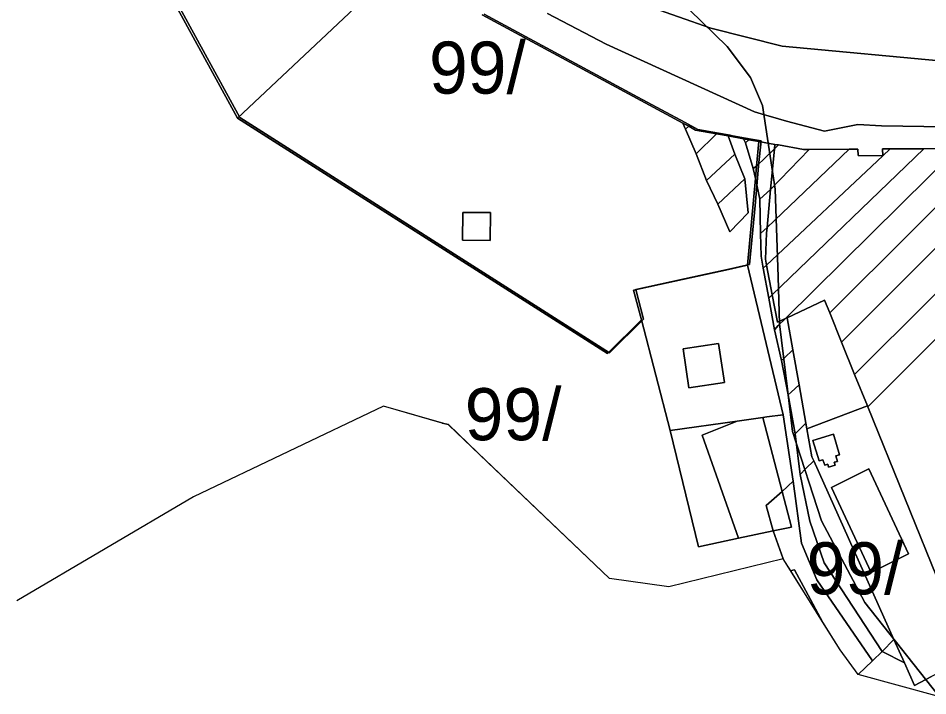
# Model space of a CAD drawing. Extents: x -535894 to -532827, y -1165802 to -1163635.
# Drawn here: x -533561 to -533298.8, y -1165099.9 to -1164904.6 of the extents above; entities that cross this region are included whole.
import ezdxf

# ---------------------------------------------------------------- set-up
doc = ezdxf.new("R2010")
doc.units = 0
for name, color, linetype in [('BPEJ_s', 7, 'Continuous'), ('orna_s', 7, 'Continuous'), ('ostatni_s', 7, 'Continuous'), ('PUPFL_s', 7, 'Continuous'), ('sad_s', 7, 'Continuous'), ('trav_porost_s', 7, 'Continuous'), ('voda_s', 7, 'Continuous'), ('zahrada_s', 7, 'Continuous')]:
    doc.layers.add(name, color=color, linetype=linetype)

msp = doc.modelspace()

# ---------------------------------------------------------------- linework, layer by layer
at = {"layer": 'BPEJ_s'}
for points in [[(-533522.095, -1164887.508), (-533497.114, -1164933.287), (-533390.513, -1165001.084), (-533380.721, -1164991.378), (-533382.945, -1164982.87), (-533368.897, -1164979.776), (-533355.644, -1164976.854), (-533351.891, -1164976.035), (-533350.116, -1164975.638), (-533348.56, -1164958.614), (-533347.837, -1164950.711), (-533347.512, -1164947.155), (-533346.817, -1164939.999), (-533349.698, -1164939.487), (-533351.256, -1164939.202), (-533355.068, -1164938.512), (-533355.703, -1164938.397), (-533359.057, -1164937.792), (-533365.083, -1164936.699), (-533368.736, -1164934.723), (-533382.308, -1164927.394), (-533426.603, -1164903.475)], [(-533426.603, -1164903.475), (-533382.308, -1164927.394), (-533368.736, -1164934.723), (-533365.083, -1164936.699), (-533359.057, -1164937.792), (-533355.703, -1164938.397), (-533355.068, -1164938.512), (-533351.256, -1164939.202), (-533349.698, -1164939.487), (-533346.817, -1164939.999), (-533347.512, -1164947.155), (-533347.837, -1164950.711), (-533348.56, -1164958.614), (-533350.116, -1164975.638), (-533351.891, -1164976.035), (-533355.644, -1164976.854), (-533368.897, -1164979.776), (-533382.945, -1164982.87), (-533380.721, -1164991.378), (-533390.513, -1165001.084), (-533497.114, -1164933.287), (-533522.095, -1164887.508)], [(-533367.42, -1164902.28), (-533356.59, -1164912.8), (-533349.9, -1164921.72), (-533346.4, -1164929.841), (-533342.74, -1164953.89), (-533341.908, -1164979.159), (-533341.46, -1164992.76), (-533339.243, -1165011.507), (-533337.792, -1165023.782), (-533329.361, -1165049.46), (-533316.93, -1165073.03), (-533295.745, -1165099.748)], [(-533295.745, -1165099.748), (-533316.93, -1165073.03), (-533329.361, -1165049.46), (-533337.792, -1165023.782), (-533339.243, -1165011.507), (-533341.46, -1164992.76), (-533341.908, -1164979.159), (-533342.74, -1164953.89), (-533346.4, -1164929.841), (-533349.9, -1164921.72), (-533356.59, -1164912.8), (-533367.42, -1164902.28)], [(-533296.36, -1165099.92), (-533318.84, -1165093.8), (-533324, -1165086.69), (-533329.073, -1165078.587), (-533333.905, -1165069.717), (-533333.909, -1165069.71), (-533337.21, -1165063.65), (-533337.643, -1165063.747), (-533338.274, -1165063.889), (-533340.42, -1165060.46), (-533373.45, -1165068.48), (-533390.5, -1165066.09), (-533425.693, -1165032.564), (-533436.87, -1165021.7), (-533438.763, -1165021.308), (-533455.65, -1165016.42), (-533510.43, -1165042.58), (-533561.35, -1165072.56)]]:
    msp.add_lwpolyline(points, dxfattribs=at)
for points in [[(-533436.87, -1165021.7), (-533425.693, -1165032.564), (-533436.96, -1165021.83), (-533438.763, -1165021.308)], [(-533333.905, -1165069.717), (-533329.073, -1165078.587), (-533338.274, -1165063.889), (-533337.643, -1165063.747), (-533337.21, -1165063.65), (-533333.909, -1165069.71)]]:
    msp.add_lwpolyline(points, close=True, dxfattribs=at)
at = {"layer": 'orna_s'}
for points in [[(-533149.26, -1164901.65), (-533141.88, -1164917.25), (-533157.58, -1164933.38), (-533260.52, -1165035.2), (-533294.68, -1165069.27), (-533316.06, -1165016.63), (-533241.31, -1164941.86), (-533238.5, -1164941.84), (-533229.28, -1164940.77)], [(-533342.95, -1164942.3), (-533341.8, -1164941.18), (-533334.55, -1164942.49), (-533332.94, -1164942.48), (-533344.05, -1164954.01)], [(-533342.83, -1164941), (-533341.8, -1164941.18), (-533342.95, -1164942.3)], [(-533321.4, -1164942.4), (-533318.89, -1164942.38), (-533318.86, -1164944.25), (-533311.76, -1164944.33), (-533345.25, -1164975.83), (-533345.58, -1164974.08), (-533345.23, -1164966.6), (-533345.07, -1164964.92)], [(-533309.61, -1164942.31), (-533299.86, -1164942.25), (-533343.59, -1164984.36), (-533345.25, -1164975.83), (-533311.76, -1164944.33)], [(-533332.94, -1164942.48), (-533321.4, -1164942.4), (-533345.07, -1164964.92), (-533344.05, -1164954.01)], [(-533299.86, -1164942.25), (-533290.22, -1164942.19), (-533339.81, -1164991.22), (-533342.06, -1164992.28), (-533343.59, -1164984.36)], [(-533290.22, -1164942.19), (-533279.34, -1164942.12), (-533327.03, -1164989.6), (-533328.55, -1164985.88), (-533339.3, -1164990.98), (-533339.81, -1164991.22)], [(-533279.34, -1164942.12), (-533267.6, -1164942.04), (-533323.61, -1164998.03), (-533327.03, -1164989.6)], [(-533267.6, -1164942.04), (-533254.19, -1164941.95), (-533319.84, -1165007.34), (-533323.61, -1164998.03)], [(-533254.19, -1164941.95), (-533241.31, -1164941.86), (-533316.06, -1165016.63), (-533316.16, -1165016.4), (-533319.84, -1165007.34)], [(-533311.84, -1164942.33), (-533309.61, -1164942.31), (-533311.76, -1164944.33)], [(-533327.03, -1164989.6), (-533323.61, -1164998.03), (-533319.84, -1165007.34), (-533316.16, -1165016.4), (-533333.62, -1165022.99), (-533333.91, -1165021.36), (-533335.87, -1165010.29), (-533337.66, -1165000.19), (-533339.3, -1164990.98), (-533328.55, -1164985.88)], [(-533353.73, -1165020.77), (-533346.35, -1165019.74), (-533340.73, -1165041.06), (-533345.32, -1165045.1), (-533343.29, -1165052.42), (-533353.28, -1165054.53), (-533363.82, -1165024.85)], [(-533345.15, -1165019.57), (-533340.49, -1165018.91), (-533337.57, -1165038.08), (-533340.73, -1165041.06), (-533346.35, -1165019.74)], [(-533345.32, -1165045.1), (-533340.73, -1165041.06), (-533338.04, -1165051.31), (-533343.29, -1165052.42)]]:
    msp.add_lwpolyline(points, close=True, dxfattribs=at)
at = {"layer": 'ostatni_s'}
for points in [[(-533427.21, -1164903.65), (-533369.34, -1164934.9), (-533368.62, -1164936.59), (-533365.53, -1164943.74), (-533362.54, -1164951.44), (-533359.28, -1164958.21), (-533355.82, -1164966.23), (-533350.5, -1164960.74), (-533351.5, -1164950.92), (-533354.34, -1164943.84), (-533356.31, -1164938.57), (-533351.86, -1164939.38), (-533351.34, -1164940.58), (-533349.07, -1164947.93), (-533348.45, -1164950.88), (-533350.73, -1164975.81), (-533352.5, -1164976.21), (-533356.25, -1164977.03), (-533369.51, -1164979.95), (-533383.55, -1164983.05), (-533381.33, -1164991.55), (-533391.12, -1165001.26), (-533497.72, -1164933.47), (-533454.32, -1164892.58)], [(-533147.32, -1164895.13), (-533230.7, -1164935.9), (-533238.8, -1164936.84), (-533312.12, -1164935.66), (-533318.96, -1164935.26), (-533328.53, -1164937.19), (-533339.52, -1164934.29), (-533341.76, -1164933.66), (-533346.78, -1164932.24), (-533348.75, -1164931.67), (-533391.45, -1164912.18), (-533408.38, -1164903.25)], [(-533408.38, -1164903.25), (-533391.45, -1164912.18), (-533348.75, -1164931.67), (-533346.78, -1164932.24), (-533341.76, -1164933.66), (-533339.52, -1164934.29), (-533328.53, -1164937.19), (-533318.96, -1164935.26), (-533312.12, -1164935.66), (-533238.8, -1164936.84), (-533230.7, -1164935.9), (-533147.32, -1164895.13)], [(-533389.23, -1164897.67), (-533361.33, -1164907.54), (-533340.78, -1164912.67), (-533291.28, -1164917.31), (-533261.61, -1164914.36), (-533236.41, -1164909.7), (-533192.2, -1164894.47)], [(-533290.22, -1164942.19), (-533299.86, -1164942.25), (-533309.61, -1164942.31), (-533311.84, -1164942.33), (-533311.76, -1164944.33), (-533318.86, -1164944.25), (-533318.89, -1164942.38), (-533321.4, -1164942.4), (-533332.94, -1164942.48), (-533334.55, -1164942.49), (-533341.8, -1164941.18), (-533342.83, -1164941), (-533347.43, -1164940.17), (-533350.31, -1164939.66), (-533351.86, -1164939.38), (-533356.31, -1164938.57), (-533359.67, -1164937.97), (-533365.69, -1164936.87), (-533367.68, -1164935.8), (-533369.34, -1164934.9), (-533427.21, -1164903.65)], [(-533296.36, -1165099.92), (-533318.84, -1165093.8), (-533314.71, -1165089.88), (-533311.86, -1165087.17), (-533305.48, -1165090.39), (-533302.55, -1165096.94), (-533297.64, -1165094.39)]]:
    msp.add_lwpolyline(points, dxfattribs=at)
for points in [[(-533367.68, -1164935.8), (-533368.62, -1164936.59), (-533369.34, -1164934.9)], [(-533368.62, -1164936.59), (-533367.68, -1164935.8), (-533365.69, -1164936.87), (-533359.67, -1164937.97), (-533365.53, -1164943.74)], [(-533359.67, -1164937.97), (-533356.31, -1164938.57), (-533354.34, -1164943.84), (-533362.54, -1164951.44), (-533365.53, -1164943.74)], [(-533351.86, -1164939.38), (-533350.31, -1164939.66), (-533351.34, -1164940.58)], [(-533350.31, -1164939.66), (-533347.43, -1164940.17), (-533348.12, -1164947.33), (-533349.07, -1164947.93), (-533351.34, -1164940.58)], [(-533347.43, -1164940.17), (-533342.83, -1164941), (-533342.95, -1164942.3), (-533348.12, -1164947.33)], [(-533354.34, -1164943.84), (-533351.5, -1164950.92), (-533359.28, -1164958.21), (-533362.54, -1164951.44)], [(-533348.12, -1164947.33), (-533342.95, -1164942.3), (-533344.05, -1164954.01), (-533347.18, -1164956.81), (-533348.45, -1164950.88)], [(-533349.07, -1164947.93), (-533348.12, -1164947.33), (-533348.45, -1164950.88)], [(-533359.28, -1164958.21), (-533351.5, -1164950.92), (-533350.5, -1164960.74), (-533355.82, -1164966.23)], [(-533347.18, -1164956.81), (-533346.96, -1164966.72), (-533346.81, -1164973.18), (-533346.18, -1164976.7), (-533344.61, -1164985.36), (-533342.97, -1164994.5), (-533340.92, -1165003.34), (-533339.05, -1165013.22), (-533337.02, -1165024.42), (-533335.51, -1165036.11), (-533332.78, -1165049.58), (-533328.63, -1165061.62), (-533311.86, -1165087.17), (-533314.71, -1165089.88), (-533330.78, -1165066.5), (-533335.17, -1165055.93), (-533337.57, -1165038.08), (-533340.49, -1165018.91), (-533350.73, -1164975.81), (-533348.45, -1164950.88)], [(-533347.18, -1164956.81), (-533344.05, -1164954.01), (-533345.07, -1164964.92), (-533346.96, -1164966.72)], [(-533432.79, -1164960.61), (-533432.86, -1164968.61), (-533424.86, -1164968.68), (-533424.79, -1164960.67)], [(-533432.79, -1164960.61), (-533424.79, -1164960.67), (-533424.86, -1164968.68), (-533432.86, -1164968.61)], [(-533345.07, -1164964.92), (-533345.23, -1164966.6), (-533345.58, -1164974.08), (-533345.25, -1164975.83), (-533346.18, -1164976.7), (-533346.81, -1164973.18), (-533346.96, -1164966.72)], [(-533346.18, -1164976.7), (-533345.25, -1164975.83), (-533343.59, -1164984.36), (-533344.61, -1164985.36)], [(-533344.61, -1164985.36), (-533343.59, -1164984.36), (-533342.06, -1164992.28), (-533339.81, -1164991.22), (-533341.87, -1164993.25), (-533342.97, -1164994.5)], [(-533339.3, -1164990.98), (-533337.66, -1165000.19), (-533340.08, -1165002.52), (-533340.92, -1165003.34), (-533342.97, -1164994.5), (-533341.87, -1164993.25), (-533339.81, -1164991.22)], [(-533369.3, -1164999.94), (-533359.07, -1164998.38), (-533357.35, -1165009.59), (-533367.61, -1165011.14)], [(-533340.08, -1165002.52), (-533337.66, -1165000.19), (-533335.87, -1165010.29), (-533338.16, -1165012.4), (-533339.05, -1165013.22), (-533340.92, -1165003.34)], [(-533338.16, -1165012.4), (-533335.87, -1165010.29), (-533333.91, -1165021.36), (-533336.02, -1165023.46), (-533337.02, -1165024.42), (-533339.05, -1165013.22)], [(-533316.06, -1165016.63), (-533294.68, -1165069.27), (-533291.2, -1165077.84), (-533287.25, -1165087.56), (-533286.76, -1165088.76), (-533290.36, -1165090.63), (-533297.64, -1165094.39), (-533302.55, -1165096.94), (-533305.48, -1165090.39), (-533308.51, -1165083.67), (-533331.65, -1165032.22), (-533332.19, -1165031.01), (-533333.62, -1165022.99), (-533316.16, -1165016.4)], [(-533333.62, -1165022.99), (-533332.19, -1165031.01), (-533331.65, -1165032.22), (-533333.89, -1165034.46), (-533335.51, -1165036.11), (-533337.02, -1165024.42), (-533336.02, -1165023.46), (-533333.91, -1165021.36)], [(-533325.97, -1165024.54), (-533331.86, -1165026.33), (-533330.07, -1165032.22), (-533328.97, -1165031.89), (-533328.48, -1165033.47), (-533327.6, -1165033.2), (-533327.35, -1165034.03), (-533325.47, -1165033.45), (-533325.72, -1165032.63), (-533324.83, -1165032.37), (-533325.31, -1165030.77), (-533324.22, -1165030.44)], [(-533325.97, -1165024.54), (-533324.22, -1165030.44), (-533325.31, -1165030.77), (-533324.83, -1165032.37), (-533325.72, -1165032.63), (-533325.47, -1165033.45), (-533327.35, -1165034.03), (-533327.6, -1165033.2), (-533328.48, -1165033.47), (-533328.97, -1165031.89), (-533330.07, -1165032.22), (-533331.86, -1165026.33)], [(-533333.89, -1165034.46), (-533331.65, -1165032.22), (-533308.51, -1165083.67), (-533311.86, -1165087.17), (-533328.63, -1165061.62), (-533332.78, -1165049.58), (-533335.51, -1165036.11)], [(-533326.51, -1165039.93), (-533315.1, -1165064.39), (-533304.34, -1165059.01), (-533315.79, -1165034.5)], [(-533326.51, -1165039.93), (-533315.79, -1165034.5), (-533304.34, -1165059.01), (-533315.1, -1165064.39)], [(-533337.57, -1165038.08), (-533335.17, -1165055.93), (-533330.78, -1165066.5), (-533314.71, -1165089.88), (-533318.84, -1165093.8), (-533324, -1165086.69), (-533340.42, -1165060.46), (-533343.29, -1165052.42), (-533338.04, -1165051.31), (-533340.73, -1165041.06)], [(-533311.86, -1165087.17), (-533308.51, -1165083.67), (-533305.48, -1165090.39)]]:
    msp.add_lwpolyline(points, close=True, dxfattribs=at)
at = {"layer": 'PUPFL_s'}
msp.add_lwpolyline([(-533516.99, -1164867.54), (-533454.32, -1164892.58), (-533497.72, -1164933.47), (-533522.7, -1164887.69), (-533553.28, -1164851.89)], close=True, dxfattribs=at)
at = {"layer": 'sad_s'}
msp.add_lwpolyline([(-533596.46, -1164833.25), (-533553.28, -1164851.89), (-533522.7, -1164887.69), (-533497.72, -1164933.47), (-533391.12, -1165001.26), (-533381.33, -1164991.55), (-533372.98, -1165023.48), (-533364.81, -1165056.97), (-533353.28, -1165054.53), (-533343.29, -1165052.42), (-533340.42, -1165060.46), (-533373.45, -1165068.48), (-533390.5, -1165066.09), (-533436.96, -1165021.83), (-533455.65, -1165016.42), (-533510.43, -1165042.58), (-533561.35, -1165072.56)], dxfattribs=at)
at = {"layer": 'trav_porost_s'}
for points in [[(-533350.73, -1164975.81), (-533340.49, -1165018.91), (-533345.15, -1165019.57), (-533346.35, -1165019.74), (-533353.73, -1165020.77), (-533372.98, -1165023.48), (-533381.33, -1164991.55), (-533383.55, -1164983.05), (-533369.51, -1164979.95), (-533356.25, -1164977.03), (-533352.5, -1164976.21)], [(-533369.3, -1164999.94), (-533367.61, -1165011.14), (-533357.35, -1165009.59), (-533359.07, -1164998.38)]]:
    msp.add_lwpolyline(points, close=True, dxfattribs=at)
at = {"layer": 'voda_s'}
msp.add_lwpolyline([(-533192.2, -1164894.47), (-533236.41, -1164909.7), (-533261.61, -1164914.36), (-533291.28, -1164917.31), (-533340.78, -1164912.67), (-533361.33, -1164907.54), (-533389.23, -1164897.67)], dxfattribs=at)
at = {"layer": 'zahrada_s'}
msp.add_lwpolyline([(-533372.98, -1165023.48), (-533353.73, -1165020.77), (-533363.82, -1165024.85), (-533353.28, -1165054.53), (-533364.81, -1165056.97)], close=True, dxfattribs=at)

# ---------------------------------------------------------------- texts
at = {"layer": 'BPEJ_s'}
for p in [(-533442.519, -1164926.393), (-533432.228, -1165026.275), (-533333.673, -1165070.69)]:
    msp.add_text('99/', height=15, dxfattribs=at).set_placement(p)

doc.saveas('drawing.dxf')
